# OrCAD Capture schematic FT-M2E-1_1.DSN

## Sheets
1 INDEX: title: 01-INDEX; rev: 1.1
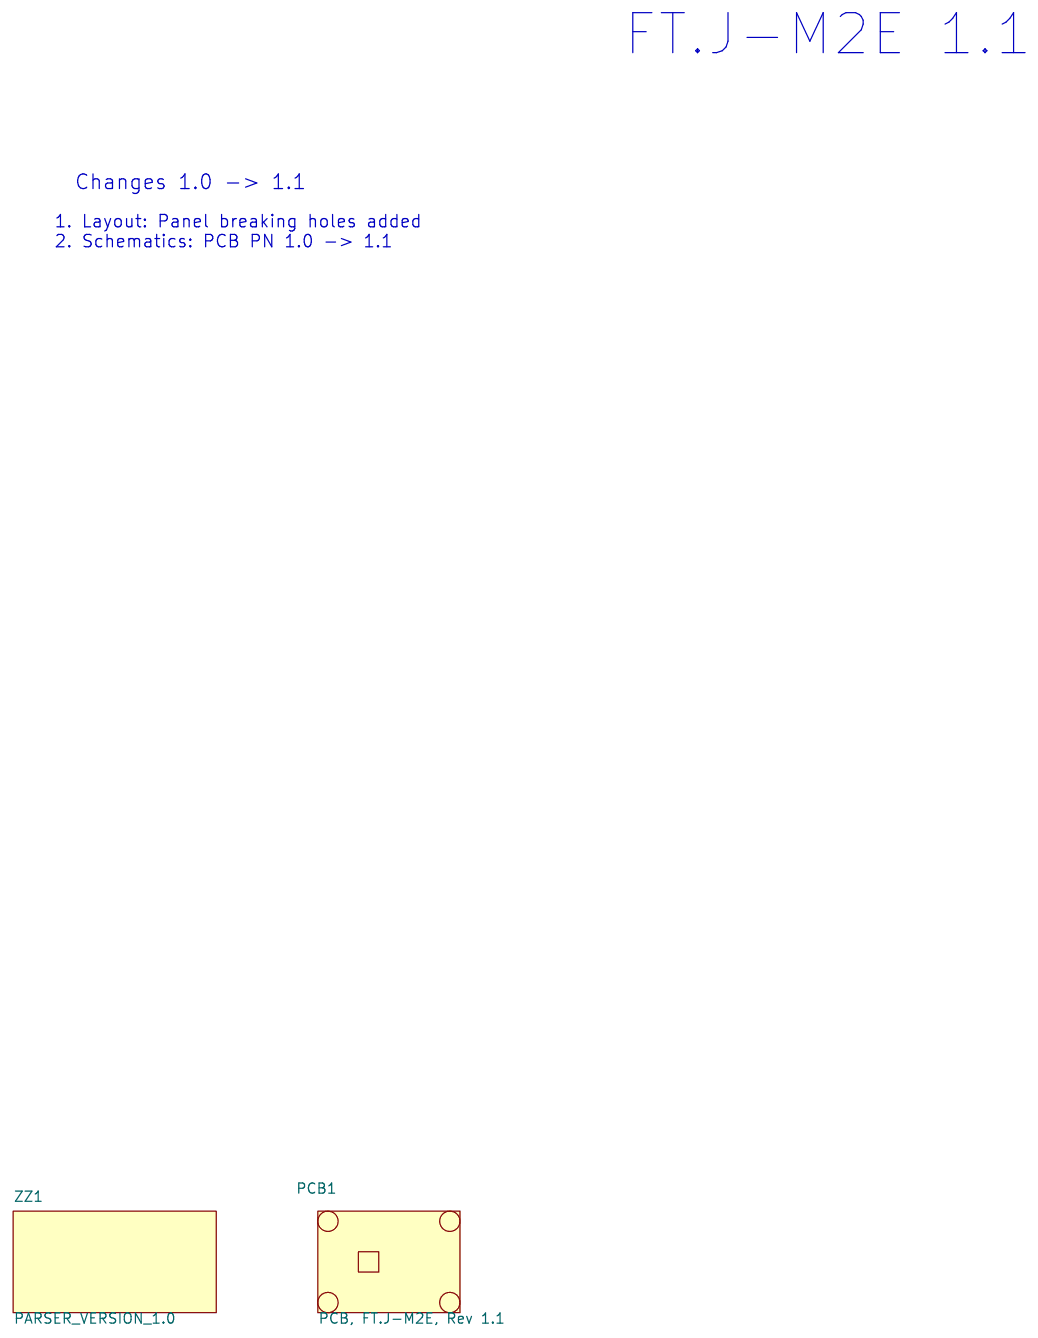
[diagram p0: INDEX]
2 TRIP: size A; title: 02-TRIP
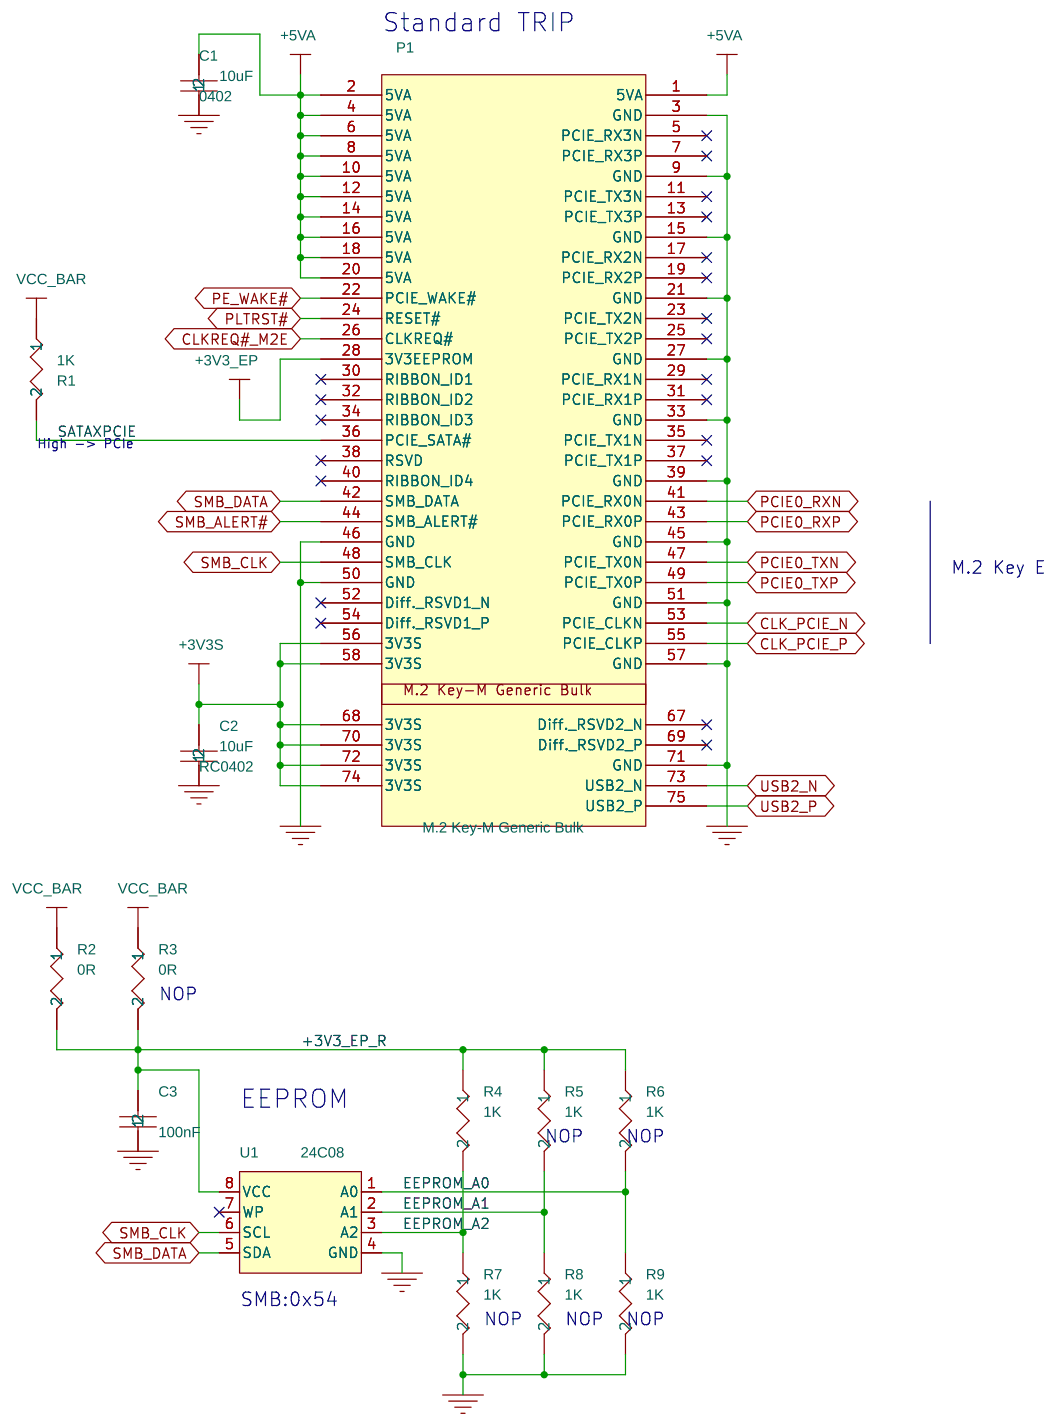
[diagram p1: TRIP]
3 M.2 Key E: size A4; title: 04-M.2 Key B/E
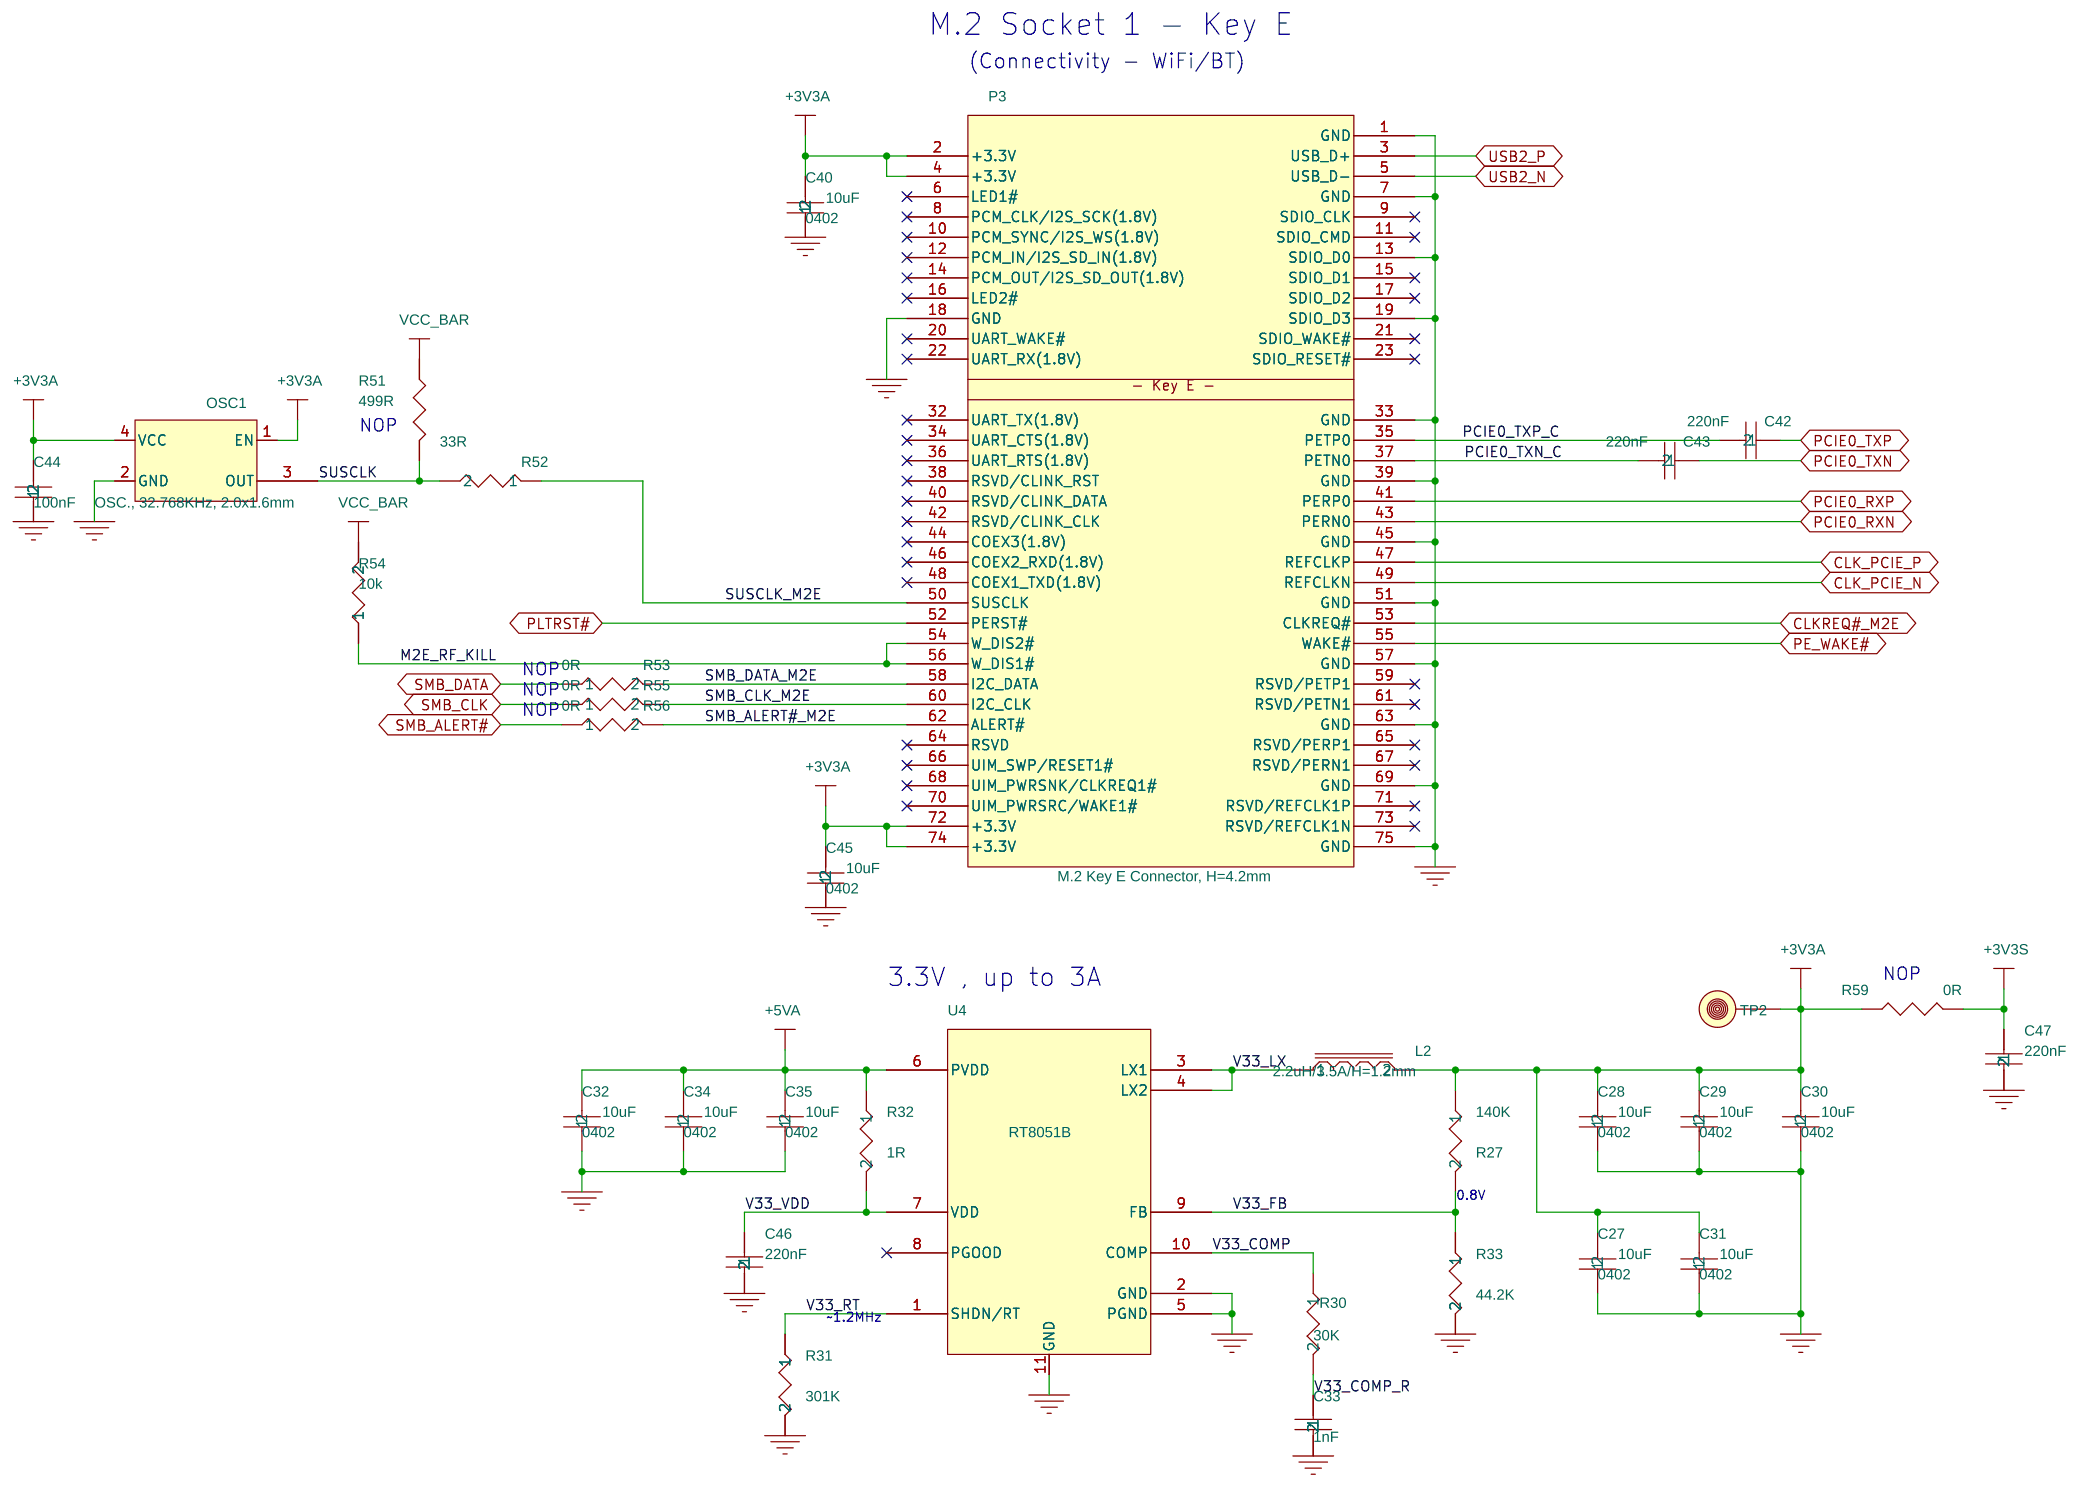
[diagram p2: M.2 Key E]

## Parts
sheet INDEX
PCB1  PCB, FT.J-M2E, Rev 1.1
ZZ1  PARSER_VERSION_1.0
sheet M.2 Key E
C27  10uF  [0402]
C28  10uF  [0402]
C29  10uF  [0402]
C30  10uF  [0402]
C31  10uF  [0402]
C32  10uF  [0402]
C33  1nF  [RC0402]
C34  10uF  [0402]
C35  10uF  [0402]
C40  10uF  [0402]
C42  220nF  [RC0402]
C43  220nF  [RC0402]
C44  100nF  [RC0402]
C45  10uF  [0402]
C46  220nF  [RC0402]
C47  220nF  [RC0402]
L2  2.2uH/3.5A/H=1.2mm  [IND4_3x4_7SM]
OSC1  OSC., 32.768KHz, 2.0x1.6mm  [OSC3225]
P3  M.2 Key E Connector, H=4.2mm  [NGFF67P4HEkeySM]
R27  140K  [RC0402]
R30  30K  [RC0402]
R31  301K  [RC0402]
R32  1R  [RC0402]
R33  44.2K  [RC0402]
R51  499R  [RC0402]
R52  33R  [RC0402]
R53  0R  [RC0402]
R54  10k  [RC0402]
R55  0R  [RC0402]
R56  0R  [RC0402]
R59  0R  [RC0402]
TP2  TP
U4  RT8051B  [DFN3x3-10]
sheet TRIP
C1  10uF  [0402]
C2  10uF  [RC0402]
C3  100nF  [RC0402]
P1  M.2 Key-M Generic Bulk  [NGFF67P8HMkeySM]
R1  1K  [RC0402]
R2  0R  [RC0402]
R3  0R  [RC0402]
R4  1K  [RC0402]
R5  1K  [RC0402]
R6  1K  [RC0402]
R7  1K  [RC0402]
R8  1K  [RC0402]
R9  1K  [RC0402]
U1  24C08  [MO-229VCED-2]

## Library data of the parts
PCB1 = SBC-iHSW_Rev_1.0: CLABCONF0: FT.J-M2E; P/N: 188C03441U
ZZ1 = PARSER_VERSION_1.0: CLABCONF0: FT.J-M2E
C27 = 100nF,_10V,_X7R,_10%,_0402_4: CLABCONF0: FT.J-M2E; P/N: 151B10600S
C28 = 100nF,_10V,_X7R,_10%,_0402_6: CLABCONF0: FT.J-M2E; P/N: 151B10600S
C29 = 100nF,_10V,_X7R,_10%,_0402_7: CLABCONF0: FT.J-M2E; P/N: 151B10600S
C30 = 100nF,_10V,_X7R,_10%,_0402_8: CLABCONF0: FT.J-M2E; P/N: 151B10600S
C31 = 100nF,_10V,_X7R,_10%,_0402_10: CLABCONF0: FT.J-M2E; P/N: 151B10600S
C1 C32 = 100nF,_10V,_X7R,_10%,_0402: CLABCONF0: FT.J-M2E; P/N: 151B10600S
C33 = 22nF,_10V,_X7R,_10%,_0402: CLABCONF0: FT.J-M2E; P/N: 151D10200S
C2 C34 = 100nF,_10V,_X7R,_10%,_0402_1: CLABCONF0: FT.J-M2E; P/N: 151B10600S
C35 = 100nF,_10V,_X7R,_10%,_0402_2: CLABCONF0: FT.J-M2E; P/N: 151B10600S
C40 = 100nF,_10V,_X7R,_10%,_0402_13: CLABCONF0: FT.J-M2E; P/N: 151B10600S
C42 = 100nF,_10V,_X7R,_10%,_0402_9: CLABCONF0: FT.J-M2E; P/N: 151C22400S
C43 = 100nF,_10V,_X7R,_10%,_0402_3: CLABCONF0: FT.J-M2E; P/N: 151C22400S
C44 = 100nF,_10V,_X7R,_10%,_0402_12: CLABCONF0: FT.J-M2E; P/N: 151B10400S
C45 = 100nF,_10V,_X7R,_10%,_0402_14: CLABCONF0: FT.J-M2E; P/N: 151B10600S
C46 = 100nF,_10V,_X7R,_10%,_0402_5: CLABCONF0: FT.J-M2E; P/N: 151C22400S
C47 = 100nF,_10V,_X7R,_10%,_0402_11: CLABCONF0: FT.J-M2E; P/N: 151C22400S
L2 = Ind,_2.2uH,_3A_5A,_58_mOhm: CLABCONF0: FT.J-M2E; P/N: 147A2R206S
OSC1 = 25MHz,50PPM,OSC3225,_3.3V: CLABCONF0: FT.J-M2E; P/N: 141C32300I
P3 = M.2_Key_E_Connector: CLABCONF0: FT.J-M2E; P/N: 182K06701S
R27 = 4.02K,1%,0402_3: CLABCONF0: FT.J-M2E; P/N: 161C14031S
R30 = 4.02K,1%,0402_1: CLABCONF0: FT.J-M2E; P/N: 161C30021S
R31 = 4.02K,1%,0402_2: CLABCONF0: FT.J-M2E; P/N: 161C30131S
R32 = 4.02K,1%,0402_4: CLABCONF0: FT.J-M2E; P/N: 161C1R001S
R33 = 4.02K,1%,0402: CLABCONF0: FT.J-M2E; P/N: 161C44221S
R51 = RESISTOR: CLABCONF0: NOP; P/N: 161C49901S
R52 = 348R,1%,0402,1_16W: CLABCONF0: FT.J-M2E; P/N: 161C33R05S
R53 = 0R_2: CLABCONF0: NOP
R54 = 1M_,5%,_0402: CLABCONF0: FT.J-M2E; P/N: 161C10021S
R55 = 0R_1: CLABCONF0: NOP; OriginalSymbolOrigin: 100uF
R56 = 0R: CLABCONF0: NOP; OriginalSymbolOrigin: 100uF
R59 = 10K,1%,0402,1_16W_0: CLABCONF0: NOP; P/N: 161C00005S
TP2 = TP_SMT: CLABCONF0: FT.J-M2E
U4 = RT8051B_4: CLABCONF0: FT.J-M2E; P/N: 123V5R004S
C3 = 15pF,_50V,_NPO,_5%,_0402: CLABCONF0: FT.J-M2E; P/N: 151B10400S
P1 = M.2_Key-M_Generic_Bulk: CLABCONF0: FT.J-M2E; P/N: 182K06700S
R1 = 348R,1%,0402,1_16W_5: CLABCONF0: FT.J-M2E; P/N: 161C10011S
R2 = 348R,1%,0402,1_16W_7: CLABCONF0: FT.J-M2E; P/N: 161C00005S
R3 = 348R,1%,0402,1_16W_6: CLABCONF0: NOP; P/N: 161C00005S
R4 = 348R,1%,0402,1_16W_1: CLABCONF0: FT.J-M2E; P/N: 161C10011S
R5 = 348R,1%,0402,1_16W_2: CLABCONF0: NOP; P/N: 161C10011S
R6 = 348R,1%,0402,1_16W: CLABCONF0: NOP; P/N: 161C10011S
R7 = 348R,1%,0402,1_16W_8: CLABCONF0: NOP; P/N: 161C10011S
R8 = 348R,1%,0402,1_16W_4: CLABCONF0: NOP; P/N: 161C10011S
R9 = 348R,1%,0402,1_16W_3: CLABCONF0: NOP; P/N: 161C10011S
U1 = 24C02,_serial_EE,_2KB,_I2C: CLABCONF0: FT.J-M2E; P/N: 111S31000S

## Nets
+3V3_EP: P1.28(3V3EEPROM) R2.1
+3V3_EP_R: C3.2 R2.2 R3.2 R4.1 R5.1 R6.1 U1.8(VCC)
+3V3A: C27.2 C28.2 C29.2 C30.2 C31.2 C40.2 C44.2 C45.2 L2.2 OSC1.1(EN) OSC1.4(VCC) P3.2(+3.3V) P3.4(+3.3V) P3.72(+3.3V) P3.74(+3.3V) R27.1 R51.1 R54.2 R59.1 TP2.1
+3V3S: C2.2 C47.1 P1.56(3V3S) P1.58(3V3S) P1.68(3V3S) P1.70(3V3S) P1.72(3V3S) P1.74(3V3S) R1.1 R3.1 R59.2
+5VA: C1.2 C32.2 C34.2 C35.2 P1.1(5VA) P1.2(5VA) P1.4(5VA) P1.6(5VA) P1.8(5VA) P1.10(5VA) P1.12(5VA) P1.14(5VA) P1.16(5VA) P1.18(5VA) P1.20(5VA) R32.1 U4.6(PVDD)
GND: C1.1 C2.1 C3.1 C27.1 C28.1 C29.1 C30.1 C31.1 C32.1 C33.2 C34.1 C35.1 C40.1 C44.1 C45.1 C46.2 C47.2 OSC1.2(GND) P1.3(GND) P1.9(GND) P1.15(GND) P1.21(GND) P1.27(GND) P1.33(GND) P1.39(GND) P1.45(GND) P1.46(GND) P1.50(GND) P1.51(GND) P1.57(GND) P1.71(GND) P3.1(GND) P3.7(GND) P3.13(SDIO_D0) P3.18(GND) P3.19(SDIO_D3) P3.33(GND) P3.39(GND) P3.45(GND) P3.51(GND) P3.57(GND) P3.63(GND) P3.69(GND) P3.75(GND) R7.2 R8.2 R9.2 R31.2 R33.2 U1.4(GND) U4.2(GND) U4.5(PGND) U4.11(GND)
V33_COMP: R30.1 U4.10(COMP)
V33_COMP_R: C33.1 R30.2
V33_FB: R27.2 R33.1 U4.9(FB)
V33_LX: L2.1 U4.3(LX1) U4.4(LX2)
V33_RT: R31.1 U4.1(SHDN/RT)
V33_VDD: C46.1 R32.2 U4.7(VDD)
CLK_PCIE_N: P1.53(PCIE_CLKN) P3.49(REFCLKN)
CLK_PCIE_P: P1.55(PCIE_CLKP) P3.47(REFCLKP)
CLKREQ#_M2E: P1.26(CLKREQ#) P3.53(CLKREQ#)
EEPROM_A0: R6.2 R9.1 U1.1(A0)
EEPROM_A1: R5.2 R8.1 U1.2(A1)
EEPROM_A2: R4.2 R7.1 U1.3(A2)
M2E_RF_KILL: P3.54(W_DIS2#) P3.56(W_DIS1#) R54.1
PCIE0_RXN: P1.41(PCIE_RX0N) P3.43(PERN0)
PCIE0_RXP: P1.43(PCIE_RX0P) P3.41(PERP0)
PCIE0_TXN: C43.1 P1.47(PCIE_TX0N)
PCIE0_TXN_C: C43.2 P3.37(PETN0)
PCIE0_TXP: C42.1 P1.49(PCIE_TX0P)
PCIE0_TXP_C: C42.2 P3.35(PETP0)
PE_WAKE#: P1.22(PCIE_WAKE#) P3.55(WAKE#)
PLTRST#: P1.24(RESET#) P3.52(PERST#)
SATAXPCIE: P1.36(PCIE_SATA#) R1.2
SMB_ALERT#: P1.44(SMB_ALERT#) R56.1
SMB_ALERT#_M2E: P3.62(ALERT#) R56.2
SMB_CLK: P1.48(SMB_CLK) R55.1 U1.6(SCL)
SMB_CLK_M2E: P3.60(I2C_CLK) R55.2
SMB_DATA: P1.42(SMB_DATA) R53.1 U1.5(SDA)
SMB_DATA_M2E: P3.58(I2C_DATA) R53.2
SUSCLK: OSC1.3(OUT) R51.2 R52.2
SUSCLK_M2E: P3.50(SUSCLK) R52.1
USB2_N: P1.73(USB2_N) P3.5(USB_D-)
USB2_P: P1.75(USB2_P) P3.3(USB_D+)

Not connected (* = marked no-connect by the designer): P1 5(PCIE_RX3N)* 7(PCIE_RX3P)* 11(PCIE_TX3N)* 13(PCIE_TX3P)* 17(PCIE_RX2N)* 19(PCIE_RX2P)* 23(PCIE_TX2N)* 25(PCIE_TX2P)* 29(PCIE_RX1N)* 30(RIBBON_ID1)* 31(PCIE_RX1P)* 32(RIBBON_ID2)* 34(RIBBON_ID3)* 35(PCIE_TX1N)* 37(PCIE_TX1P)* 38(RSVD)* 40(RIBBON_ID4)* 52(Diff._RSVD1_N)* 54(Diff._RSVD1_P)* 67(Diff._RSVD2_N)* 69(Diff._RSVD2_P)*; P3 6(LED1#)* 8(PCM_CLK/I2S_SCK(1.8V))* 9(SDIO_CLK)* 10(PCM_SYNC/I2S_WS(1.8V))* 11(SDIO_CMD)* 12(PCM_IN/I2S_SD_IN(1.8V))* 14(PCM_OUT/I2S_SD_OUT(1.8V))* 15(SDIO_D1)* 16(LED2#)* 17(SDIO_D2)* 20(UART_WAKE#)* 21(SDIO_WAKE#)* 22(UART_RX(1.8V))* 23(SDIO_RESET#)* 32(UART_TX(1.8V))* 34(UART_CTS(1.8V))* 36(UART_RTS(1.8V))* 38(RSVD/CLINK_RST)* 40(RSVD/CLINK_DATA)* 42(RSVD/CLINK_CLK)* 44(COEX3(1.8V))* 46(COEX2_RXD(1.8V))* 48(COEX1_TXD(1.8V))* 59(RSVD/PETP1)* 61(RSVD/PETN1)* 64(RSVD)* 65(RSVD/PERP1)* 66(UIM_SWP/RESET1#)* 67(RSVD/PERN1)* 68(UIM_PWRSNK/CLKREQ1#)* 70(UIM_PWRSRC/WAKE1#)* 71(RSVD/REFCLK1P)* 73(RSVD/REFCLK1N)*; U1 7(WP)*; U4 8(PGOOD)*

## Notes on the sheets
sheet 1
- FT.J-M2E 1.1
- Changes 1.0 -> 1.1
- 1. Layout: Panel breaking holes added
  2. Schematics: PCB PN 1.0 -> 1.1
sheet 2
- Standard TRIP
- High -> PCIe
- M.2 Key E
- NOP
- EEPROM
- NOP
- NOP
- SMB:0x54
- NOP
- NOP
- NOP
sheet 3
- M.2 Socket 1 - Key E
- (Connectivity - WiFi/BT)
- NOP
- NOP
- NOP
- NOP
- 3.3V , up to 3A
- NOP
- 0.8V
- ~1.2MHz
